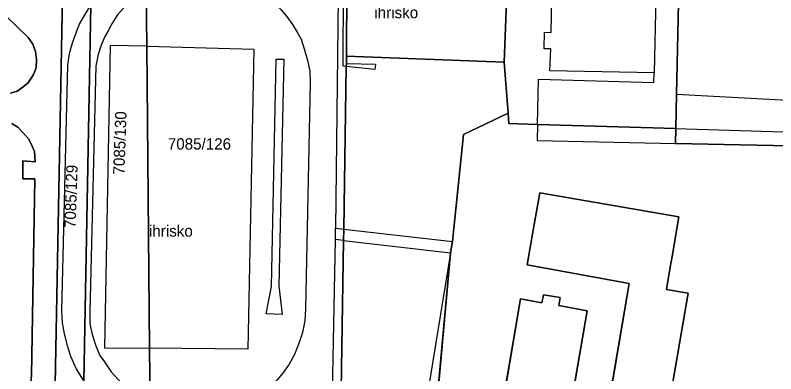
# Model space of a CAD drawing. Extents: x -266199 to -261993, y -1239047 to -1235108.
# Drawn here: x -263730.4 to -263596.4, y -1236847.2 to -1236783.9 of the extents above; entities that cross this region are included whole.
import ezdxf

# ---------------------------------------------------------------- set-up
doc = ezdxf.new("R2010")
doc.units = 0
for name, color, linetype in [('body_kn', 7, 'Continuous'), ('kladpar_druhypozemkov', 7, 'Continuous'), ('kladpar_hranice', 7, 'Continuous'), ('kladpar_parcelnecisla', 7, 'Continuous'), ('kladpar_plochy', 7, 'Continuous'), ('popisy', 7, 'Continuous'), ('zappar_hrandruhpozemk', 7, 'Continuous')]:
    doc.layers.add(name, color=color, linetype=linetype)

msp = doc.modelspace()

# ---------------------------------------------------------------- linework, layer by layer
at = {"layer": 'body_kn'}
for p, q in [((-263718.29, -1236783.97), (-263718.29, -1236783.97)), ((-263682.58, -1236784.11), (-263682.58, -1236784.11)), ((-263719.06, -1236785.4), (-263719.06, -1236785.4)), ((-263713.37, -1236785.44), (-263713.37, -1236785.44)), ((-263681.54, -1236785.56), (-263681.54, -1236785.56)), ((-263719.68, -1236786.89), (-263719.68, -1236786.89)), ((-263714.04, -1236786.68), (-263714.04, -1236786.68)), ((-263680.73, -1236786.92), (-263680.73, -1236786.92)), ((-263637.13, -1236786.94), (-263637.13, -1236786.94)), ((-263635.93, -1236786.95), (-263635.93, -1236786.95)), ((-263728.11, -1236787.85), (-263728.11, -1236787.85)), ((-263714.66, -1236787.82), (-263714.66, -1236787.82)), ((-263680.03, -1236788.17), (-263680.03, -1236788.17)), ((-263727.28, -1236789.04), (-263727.28, -1236789.04)), ((-263720.38, -1236788.88), (-263720.38, -1236788.88)), ((-263715.33, -1236789.41), (-263715.33, -1236789.41)), ((-263713.67, -1236789.25), (-263713.67, -1236789.25)), ((-263707.24, -1236789.41), (-263707.24, -1236789.41)), ((-263707.24, -1236789.41), (-263707.24, -1236789.41)), ((-263688.35, -1236789.89), (-263688.35, -1236789.89)), ((-263679.51, -1236789.88), (-263679.51, -1236789.88)), ((-263637.21, -1236789.85), (-263637.21, -1236789.85)), ((-263637.21, -1236789.85), (-263637.21, -1236789.85)), ((-263635.99, -1236789.88), (-263635.99, -1236789.88)), ((-263726.83, -1236790.3), (-263726.83, -1236790.3)), ((-263720.91, -1236790.74), (-263720.91, -1236790.74)), ((-263715.77, -1236790.87), (-263715.77, -1236790.87)), ((-263672.59, -1236791.13), (-263672.59, -1236791.13)), ((-263672.04, -1236791.15), (-263672.04, -1236791.15)), ((-263726.64, -1236791.75), (-263726.64, -1236791.75)), ((-263721.22, -1236792.66), (-263721.22, -1236792.66)), ((-263684.44, -1236791.69), (-263684.44, -1236791.69)), ((-263684.44, -1236791.69), (-263684.44, -1236791.69)), ((-263683.06, -1236791.7), (-263683.06, -1236791.7)), ((-263678.98, -1236791.69), (-263678.98, -1236791.69)), ((-263672.05, -1236792.41), (-263672.05, -1236792.41)), ((-263672.05, -1236792.41), (-263672.05, -1236792.41)), ((-263666.94, -1236792.53), (-263666.94, -1236792.53)), ((-263644.25, -1236792.2), (-263644.25, -1236792.2)), ((-263644.25, -1236792.2), (-263644.25, -1236792.2)), ((-263726.7, -1236793.22), (-263726.7, -1236793.22)), ((-263716.19, -1236792.87), (-263716.19, -1236792.87)), ((-263678.48, -1236793.75), (-263678.48, -1236793.75)), ((-263672.6, -1236792.93), (-263672.6, -1236792.93)), ((-263672.06, -1236792.98), (-263672.06, -1236792.98)), ((-263672.06, -1236792.98), (-263672.06, -1236792.98)), ((-263667.03, -1236793.48), (-263667.03, -1236793.48)), ((-263636.21, -1236793.75), (-263636.21, -1236793.75)), ((-263617.81, -1236794.08), (-263617.81, -1236794.08)), ((-263617.81, -1236794.08), (-263617.81, -1236794.08)), ((-263727.21, -1236794.39), (-263727.21, -1236794.39)), ((-263638.16, -1236795.18), (-263638.16, -1236795.18)), ((-263729.25, -1236796.75), (-263729.25, -1236796.75)), ((-263728.16, -1236795.86), (-263728.16, -1236795.86)), ((-263678.44, -1236795.8), (-263678.44, -1236795.8)), ((-263617.87, -1236795.8), (-263617.87, -1236795.8)), ((-263730.07, -1236797.34), (-263730.07, -1236797.34)), ((-263613.84, -1236797.84), (-263613.84, -1236797.84)), ((-263613.84, -1236797.84), (-263613.84, -1236797.84)), ((-263643.55, -1236801.17), (-263643.55, -1236801.17)), ((-263643.55, -1236801.17), (-263643.55, -1236801.17)), ((-263643.41, -1236803.03), (-263643.41, -1236803.03)), ((-263638.37, -1236803.18), (-263638.37, -1236803.18)), ((-263638.37, -1236803.18), (-263638.37, -1236803.18)), ((-263729.93, -1236803.67), (-263729.93, -1236803.67)), ((-263729.01, -1236804.68), (-263729.01, -1236804.68)), ((-263613.97, -1236803.91), (-263613.97, -1236803.91)), ((-263613.97, -1236803.91), (-263613.97, -1236803.91)), ((-263728, -1236805.76), (-263728, -1236805.76)), ((-263651.4, -1236804.98), (-263651.4, -1236804.98)), ((-263638.44, -1236806.04), (-263638.44, -1236806.04)), ((-263727.43, -1236806.99), (-263727.43, -1236806.99)), ((-263614.03, -1236806.55), (-263614.03, -1236806.55)), ((-263727.02, -1236807.93), (-263727.02, -1236807.93)), ((-263729.06, -1236809.61), (-263729.06, -1236809.61)), ((-263726.9, -1236809.79), (-263726.9, -1236809.79)), ((-263729.08, -1236812.8), (-263729.08, -1236812.8)), ((-263726.97, -1236812.77), (-263726.97, -1236812.77)), ((-263637.97, -1236815.26), (-263637.97, -1236815.26)), ((-263613.45, -1236819.48), (-263613.45, -1236819.48)), ((-263673.95, -1236821.5), (-263673.95, -1236821.5)), ((-263673.95, -1236821.5), (-263673.95, -1236821.5)), ((-263672.51, -1236821.66), (-263672.51, -1236821.66)), ((-263672.51, -1236821.66), (-263672.51, -1236821.66)), ((-263639.13, -1236821.86), (-263639.13, -1236821.86)), ((-263673.98, -1236823.48), (-263673.98, -1236823.48)), ((-263673.98, -1236823.48), (-263673.98, -1236823.48)), ((-263672.54, -1236823.65), (-263672.54, -1236823.65)), ((-263672.54, -1236823.65), (-263672.54, -1236823.65)), ((-263653.36, -1236823.82), (-263653.36, -1236823.82)), ((-263653.36, -1236823.82), (-263653.36, -1236823.82)), ((-263653.7, -1236825.82), (-263653.7, -1236825.82)), ((-263653.7, -1236825.82), (-263653.7, -1236825.82)), ((-263614.65, -1236826.47), (-263614.65, -1236826.47)), ((-263640.21, -1236827.97), (-263640.21, -1236827.97)), ((-263614.97, -1236828.35), (-263614.97, -1236828.35)), ((-263683.97, -1236831.63), (-263683.97, -1236831.63)), ((-263622.19, -1236831.21), (-263622.19, -1236831.21)), ((-263685.27, -1236831.75), (-263685.27, -1236831.75)), ((-263615.64, -1236832.29), (-263615.64, -1236832.29)), ((-263611.83, -1236832.93), (-263611.83, -1236832.93)), ((-263641.34, -1236833.95), (-263641.34, -1236833.95)), ((-263637.33, -1236833.24), (-263637.33, -1236833.24)), ((-263634.35, -1236833.71), (-263634.35, -1236833.71)), ((-263637.58, -1236834.64), (-263637.58, -1236834.64)), ((-263634.61, -1236835.1), (-263634.61, -1236835.1)), ((-263722.25, -1236836.07), (-263722.25, -1236836.07)), ((-263717.28, -1236836.22), (-263717.28, -1236836.22)), ((-263686.18, -1236836.61), (-263686.18, -1236836.61)), ((-263683.38, -1236836.73), (-263683.38, -1236836.73)), ((-263679.27, -1236835.7), (-263679.27, -1236835.7)), ((-263629.6, -1236836.05), (-263629.6, -1236836.05)), ((-263722.14, -1236838.2), (-263722.14, -1236838.2)), ((-263679.36, -1236837.83), (-263679.36, -1236837.83)), ((-263717.26, -1236838.35), (-263717.26, -1236838.35)), ((-263721.78, -1236840.13), (-263721.78, -1236840.13)), ((-263716.88, -1236840.25), (-263716.88, -1236840.25)), ((-263679.77, -1236839.91), (-263679.77, -1236839.91)), ((-263721.25, -1236842.16), (-263721.25, -1236842.16)), ((-263716.19, -1236842.21), (-263716.19, -1236842.21)), ((-263680.34, -1236841.67), (-263680.34, -1236841.67)), ((-263714.67, -1236842.58), (-263714.67, -1236842.58)), ((-263706.72, -1236842.67), (-263706.72, -1236842.67)), ((-263689.42, -1236842.85), (-263689.42, -1236842.85)), ((-263720.66, -1236844.07), (-263720.66, -1236844.07)), ((-263715.52, -1236843.93), (-263715.52, -1236843.93)), ((-263714.65, -1236845.04), (-263714.65, -1236845.04)), ((-263681.2, -1236843.77), (-263681.2, -1236843.77)), ((-263682.14, -1236845.45), (-263682.14, -1236845.45)), ((-263719.61, -1236846.4), (-263719.61, -1236846.4)), ((-263713.49, -1236846.79), (-263713.49, -1236846.79)), ((-263683.3, -1236847.09), (-263683.3, -1236847.09))]:
    msp.add_line(p, q, dxfattribs=at)
at = {"layer": 'kladpar_druhypozemkov'}
for p, q in [((-263711.77, -1236797.65), (-263711.77, -1236797.65)), ((-263697.3, -1236804.4), (-263697.3, -1236804.4)), ((-263719.74, -1236806.9), (-263719.74, -1236806.9)), ((-263665.1, -1236846.68), (-263665.1, -1236846.68))]:
    msp.add_line(p, q, dxfattribs=at)
at = {"layer": 'kladpar_hranice'}
for points in [[(-263613.84, -1236797.84), (-263612.64, -1236741.89), (-263612.51, -1236735.84), (-263583.74, -1236736.71), (-263585.19, -1236799.38), (-263585.32, -1236804.77), (-263585.37, -1236807.14), (-263614.03, -1236806.55), (-263613.97, -1236803.91), (-263613.84, -1236797.84)], [(-263612.64, -1236741.89), (-263613.84, -1236797.84), (-263613.97, -1236803.91), (-263638.37, -1236803.18), (-263643.41, -1236803.03), (-263643.55, -1236801.17), (-263644.25, -1236792.2), (-263643.85, -1236781.56)], [(-263716.7, -1236751.08), (-263717.28, -1236752.66), (-263717.14, -1236754.36), (-263721.61, -1236755.64), (-263721.75, -1236763.12), (-263721.85, -1236768.12), (-263723.45, -1236852.13), (-263724.24, -1236852.11)], [(-263707.61, -1236751.73), (-263707.61, -1236752.17), (-263707.61, -1236752.3), (-263707.57, -1236756.49), (-263707.39, -1236773.99), (-263707.34, -1236779.59), (-263707.24, -1236789.41), (-263706.72, -1236842.67), (-263706.62, -1236852.4), (-263706.58, -1236856.95)], [(-263706.58, -1236856.95), (-263706.62, -1236852.4), (-263706.72, -1236842.67), (-263707.24, -1236789.41), (-263707.34, -1236779.59), (-263707.39, -1236773.99), (-263707.57, -1236756.49), (-263707.61, -1236752.3), (-263707.61, -1236752.17), (-263707.61, -1236751.73)], [(-263705.51, -1236751.38), (-263705.53, -1236751.84), (-263705.62, -1236754.9), (-263706.11, -1236770.94), (-263678.03, -1236773.3), (-263673.4, -1236773.69), (-263672.79, -1236773.74), (-263672.84, -1236777.74), (-263671.99, -1236777.71), (-263671.99, -1236778.61), (-263672.04, -1236791.15), (-263672.05, -1236792.41), (-263672.06, -1236792.98), (-263672.51, -1236821.66), (-263672.54, -1236823.65), (-263673.08, -1236857.59), (-263673.25, -1236874.56), (-263674.92, -1236874.56), (-263680.06, -1236874.56), (-263682.17, -1236874.56), (-263704.55, -1236858.41), (-263706.58, -1236856.95)], [(-263717.14, -1236754.36), (-263716.6, -1236754.28), (-263716.7, -1236759.25), (-263716.78, -1236763.99), (-263717.11, -1236782.13), (-263718.32, -1236848.48), (-263718.46, -1236856.19), (-263723.45, -1236852.13), (-263721.85, -1236768.12), (-263721.75, -1236763.12), (-263721.61, -1236755.64), (-263717.14, -1236754.36)], [(-263706.58, -1236856.95), (-263718.32, -1236848.48), (-263717.11, -1236782.13), (-263716.78, -1236763.99), (-263716.7, -1236759.25), (-263716.6, -1236754.28)], [(-263643.85, -1236781.56), (-263644.25, -1236792.2), (-263672.04, -1236791.15), (-263671.99, -1236778.61)], [(-263731.24, -1236797.68), (-263730.07, -1236797.34), (-263729.25, -1236796.75), (-263728.16, -1236795.86), (-263727.21, -1236794.39), (-263726.7, -1236793.22), (-263726.64, -1236791.75), (-263726.83, -1236790.3), (-263727.28, -1236789.04), (-263728.11, -1236787.85), (-263732.1, -1236783.97)], [(-263732.1, -1236783.97), (-263728.11, -1236787.85), (-263727.28, -1236789.04), (-263726.83, -1236790.3), (-263726.64, -1236791.75), (-263726.7, -1236793.22), (-263727.21, -1236794.39), (-263728.16, -1236795.86), (-263729.25, -1236796.75), (-263730.07, -1236797.34), (-263731.24, -1236797.68)], [(-263706.58, -1236856.95), (-263704.55, -1236858.41), (-263682.17, -1236874.56), (-263680.06, -1236874.56), (-263674.92, -1236874.56), (-263673.25, -1236874.56), (-263673.08, -1236857.59), (-263672.54, -1236823.65), (-263672.51, -1236821.66), (-263672.06, -1236792.98), (-263672.05, -1236792.41), (-263672.04, -1236791.15), (-263644.25, -1236792.2)], [(-263644.25, -1236792.2), (-263643.55, -1236801.17), (-263651.4, -1236804.98), (-263653.36, -1236823.82), (-263653.7, -1236825.82), (-263657.83, -1236871.66), (-263659.27, -1236887.66), (-263659.67, -1236888.98)], [(-263659.67, -1236888.98), (-263659.27, -1236887.66), (-263657.83, -1236871.66), (-263653.7, -1236825.82), (-263653.36, -1236823.82), (-263651.4, -1236804.98), (-263643.55, -1236801.17)], [(-263643.55, -1236801.17), (-263643.41, -1236803.03), (-263638.37, -1236803.18), (-263613.97, -1236803.91), (-263614.03, -1236806.55), (-263585.37, -1236807.14), (-263579.23, -1236807.27), (-263579.09, -1236804.96), (-263566.69, -1236804.81), (-263568.91, -1236807.57), (-263570.28, -1236812.26), (-263570.64, -1236814.85), (-263598.28, -1236906.87), (-263599.02, -1236908.76)], [(-263730.99, -1236803.01), (-263729.93, -1236803.67), (-263729.01, -1236804.68), (-263728, -1236805.76), (-263727.43, -1236806.99), (-263727.02, -1236807.93), (-263726.9, -1236809.79), (-263729.06, -1236809.61), (-263729.08, -1236812.8), (-263726.97, -1236812.77), (-263727.57, -1236847.41), (-263727.8, -1236849.96), (-263728.66, -1236852.26)], [(-263724.24, -1236852.11), (-263728.66, -1236852.26), (-263727.8, -1236849.96), (-263727.57, -1236847.41), (-263726.97, -1236812.77), (-263729.08, -1236812.8), (-263729.06, -1236809.61), (-263726.9, -1236809.79), (-263727.02, -1236807.93), (-263727.43, -1236806.99), (-263728, -1236805.76), (-263729.01, -1236804.68), (-263729.93, -1236803.67), (-263730.99, -1236803.01)], [(-263616.14, -1236858.2), (-263611.83, -1236832.93), (-263615.64, -1236832.29), (-263614.97, -1236828.35), (-263614.65, -1236826.47), (-263613.45, -1236819.48), (-263637.97, -1236815.26), (-263639.13, -1236821.86), (-263640.21, -1236827.97), (-263622.19, -1236831.21), (-263626.23, -1236855)], [(-263626.23, -1236855), (-263622.19, -1236831.21), (-263640.21, -1236827.97), (-263639.13, -1236821.86), (-263637.97, -1236815.26), (-263613.45, -1236819.48), (-263614.65, -1236826.47), (-263614.97, -1236828.35), (-263615.64, -1236832.29), (-263611.83, -1236832.93), (-263616.14, -1236858.2)], [(-263632.67, -1236853.87), (-263629.6, -1236836.05), (-263634.61, -1236835.1), (-263634.35, -1236833.71), (-263637.33, -1236833.24), (-263637.58, -1236834.64), (-263641.34, -1236833.95), (-263646.51, -1236864.27)], [(-263646.51, -1236864.27), (-263641.34, -1236833.95), (-263637.58, -1236834.64), (-263637.33, -1236833.24), (-263634.35, -1236833.71), (-263634.61, -1236835.1), (-263629.6, -1236836.05), (-263632.67, -1236853.87)]]:
    msp.add_lwpolyline(points, dxfattribs=at)
at = {"layer": 'kladpar_plochy'}
for p, q in [((-263651.4, -1236804.98), (-263643.55, -1236801.17)), ((-263643.55, -1236801.17), (-263643.41, -1236803.03)), ((-263643.41, -1236803.03), (-263638.37, -1236803.18)), ((-263638.37, -1236803.18), (-263613.97, -1236803.91)), ((-263613.97, -1236803.91), (-263614.03, -1236806.55)), ((-263653.36, -1236823.82), (-263651.4, -1236804.98)), ((-263614.03, -1236806.55), (-263585.37, -1236807.14)), ((-263637.97, -1236815.26), (-263639.13, -1236821.86)), ((-263613.45, -1236819.48), (-263637.97, -1236815.26)), ((-263614.65, -1236826.47), (-263613.45, -1236819.48)), ((-263639.13, -1236821.86), (-263640.21, -1236827.97)), ((-263653.7, -1236825.82), (-263653.36, -1236823.82)), ((-263657.83, -1236871.66), (-263653.7, -1236825.82)), ((-263614.97, -1236828.35), (-263614.65, -1236826.47)), ((-263640.21, -1236827.97), (-263622.19, -1236831.21)), ((-263615.64, -1236832.29), (-263614.97, -1236828.35)), ((-263622.19, -1236831.21), (-263626.23, -1236855)), ((-263616.14, -1236858.2), (-263611.83, -1236832.93)), ((-263611.83, -1236832.93), (-263615.64, -1236832.29)), ((-263641.34, -1236833.95), (-263646.51, -1236864.27)), ((-263637.58, -1236834.64), (-263641.34, -1236833.95)), ((-263637.33, -1236833.24), (-263637.58, -1236834.64)), ((-263634.35, -1236833.71), (-263637.33, -1236833.24)), ((-263634.61, -1236835.1), (-263634.35, -1236833.71)), ((-263629.6, -1236836.05), (-263634.61, -1236835.1)), ((-263632.67, -1236853.87), (-263629.6, -1236836.05))]:
    msp.add_line(p, q, dxfattribs=at)
for points in [[(-263635.88, -1236722.21), (-263621.12, -1236719.13), (-263612.11, -1236717.26), (-263612.17, -1236719.74), (-263612.19, -1236721.02), (-263612.39, -1236730.32), (-263612.51, -1236735.84), (-263612.64, -1236741.89), (-263613.84, -1236797.84), (-263613.97, -1236803.91), (-263638.37, -1236803.18), (-263643.41, -1236803.03), (-263643.55, -1236801.17), (-263644.25, -1236792.2), (-263643.85, -1236781.56), (-263642.01, -1236781.55), (-263637.95, -1236781.74), (-263637.19, -1236749.91), (-263636.87, -1236743.09), (-263636.71, -1236739.62), (-263636.55, -1236736.35), (-263636.25, -1236729.99), (-263636.08, -1236726.31), (-263636.02, -1236724.85)], [(-263613.84, -1236797.84), (-263612.64, -1236741.89), (-263612.51, -1236735.84), (-263583.74, -1236736.71), (-263585.19, -1236799.38), (-263585.32, -1236804.77), (-263585.37, -1236807.14), (-263614.03, -1236806.55), (-263613.97, -1236803.91)], [(-263716.6, -1236754.28), (-263714.28, -1236753.91), (-263712.21, -1236752.83), (-263709.64, -1236752.07), (-263707.61, -1236751.73), (-263707.61, -1236752.17), (-263707.61, -1236752.3), (-263707.57, -1236756.49), (-263707.39, -1236773.99), (-263707.34, -1236779.59), (-263707.24, -1236789.41), (-263706.72, -1236842.67), (-263706.62, -1236852.4), (-263706.58, -1236856.95), (-263718.32, -1236848.48), (-263717.11, -1236782.13), (-263716.78, -1236763.99), (-263716.7, -1236759.25)], [(-263717.14, -1236754.36), (-263716.6, -1236754.28), (-263716.7, -1236759.25), (-263716.78, -1236763.99), (-263717.11, -1236782.13), (-263718.32, -1236848.48), (-263718.46, -1236856.19), (-263723.45, -1236852.13), (-263721.85, -1236768.12), (-263721.75, -1236763.12), (-263721.61, -1236755.64)]]:
    msp.add_lwpolyline(points, close=True, dxfattribs=at)
for points in [[(-263732.25, -1236754.6), (-263726.83, -1236753.44), (-263722, -1236752.36), (-263716.7, -1236751.08), (-263717.28, -1236752.66), (-263717.14, -1236754.36), (-263721.61, -1236755.64), (-263721.75, -1236763.12), (-263721.85, -1236768.12), (-263723.45, -1236852.13), (-263724.24, -1236852.11), (-263728.66, -1236852.26), (-263727.8, -1236849.96), (-263727.57, -1236847.41), (-263726.97, -1236812.77), (-263729.08, -1236812.8), (-263729.06, -1236809.61), (-263726.9, -1236809.79), (-263727.02, -1236807.93), (-263727.43, -1236806.99), (-263728, -1236805.76), (-263729.01, -1236804.68), (-263729.93, -1236803.67), (-263730.99, -1236803.01)], [(-263671.99, -1236778.61), (-263672.04, -1236791.15), (-263672.05, -1236792.41), (-263672.06, -1236792.98), (-263672.51, -1236821.66), (-263672.54, -1236823.65), (-263673.08, -1236857.59), (-263673.25, -1236874.56), (-263674.92, -1236874.56), (-263680.06, -1236874.56), (-263682.17, -1236874.56), (-263704.55, -1236858.41), (-263706.58, -1236856.95), (-263706.62, -1236852.4), (-263706.72, -1236842.67), (-263707.24, -1236789.41), (-263707.34, -1236779.59)], [(-263643.85, -1236781.56), (-263644.25, -1236792.2), (-263672.04, -1236791.15), (-263671.99, -1236778.61)], [(-263731.24, -1236797.68), (-263730.07, -1236797.34), (-263729.25, -1236796.75), (-263728.16, -1236795.86), (-263727.21, -1236794.39), (-263726.7, -1236793.22), (-263726.64, -1236791.75), (-263726.83, -1236790.3), (-263727.28, -1236789.04), (-263728.11, -1236787.85), (-263732.1, -1236783.97)], [(-263732.1, -1236783.97), (-263728.11, -1236787.85), (-263727.28, -1236789.04), (-263726.83, -1236790.3), (-263726.64, -1236791.75), (-263726.7, -1236793.22), (-263727.21, -1236794.39), (-263728.16, -1236795.86), (-263729.25, -1236796.75), (-263730.07, -1236797.34), (-263731.24, -1236797.68)], [(-263673.08, -1236857.59), (-263672.54, -1236823.65), (-263672.51, -1236821.66), (-263672.06, -1236792.98), (-263672.05, -1236792.41), (-263672.04, -1236791.15), (-263644.25, -1236792.2), (-263643.55, -1236801.17), (-263651.4, -1236804.98), (-263653.36, -1236823.82), (-263653.7, -1236825.82), (-263657.83, -1236871.66)], [(-263730.99, -1236803.01), (-263729.93, -1236803.67), (-263729.01, -1236804.68), (-263728, -1236805.76), (-263727.43, -1236806.99), (-263727.02, -1236807.93), (-263726.9, -1236809.79), (-263729.06, -1236809.61), (-263729.08, -1236812.8), (-263726.97, -1236812.77), (-263727.57, -1236847.41), (-263727.8, -1236849.96), (-263728.66, -1236852.26), (-263737.21, -1236847.24)], [(-263626.23, -1236855), (-263622.19, -1236831.21), (-263640.21, -1236827.97), (-263639.13, -1236821.86), (-263637.97, -1236815.26), (-263613.45, -1236819.48), (-263614.65, -1236826.47), (-263614.97, -1236828.35), (-263615.64, -1236832.29), (-263611.83, -1236832.93), (-263616.14, -1236858.2)], [(-263646.51, -1236864.27), (-263641.34, -1236833.95), (-263637.58, -1236834.64), (-263637.33, -1236833.24), (-263634.35, -1236833.71), (-263634.61, -1236835.1), (-263629.6, -1236836.05), (-263632.67, -1236853.87)]]:
    msp.add_lwpolyline(points, dxfattribs=at)
at = {"layer": 'zappar_hrandruhpozemk'}
for p, q in [((-263635.93, -1236786.95), (-263635.21, -1236749.97)), ((-263616.89, -1236750.34), (-263617.81, -1236794.08)), ((-263673.45, -1236778.74), (-263673.95, -1236821.5)), ((-263672.59, -1236791.13), (-263672.52, -1236778.62)), ((-263713.37, -1236785.44), (-263714.04, -1236786.68)), ((-263713.67, -1236789.25), (-263714.67, -1236842.58)), ((-263707.24, -1236789.41), (-263713.67, -1236789.25)), ((-263707.24, -1236789.41), (-263688.35, -1236789.89)), ((-263688.35, -1236789.89), (-263689.42, -1236842.85)), ((-263721.22, -1236792.66), (-263722.25, -1236836.07)), ((-263685.27, -1236831.75), (-263684.44, -1236791.69)), ((-263672.05, -1236792.41), (-263666.94, -1236792.53)), ((-263666.94, -1236792.53), (-263667.03, -1236793.48)), ((-263716.19, -1236792.87), (-263717.28, -1236836.22)), ((-263667.03, -1236793.48), (-263672.06, -1236792.98)), ((-263617.87, -1236795.8), (-263617.81, -1236794.08)), ((-263638.37, -1236803.18), (-263638.16, -1236795.18)), ((-263638.16, -1236795.18), (-263617.87, -1236795.8)), ((-263678.44, -1236795.8), (-263679.27, -1236835.7)), ((-263613.84, -1236797.84), (-263585.19, -1236799.38)), ((-263638.37, -1236803.18), (-263638.44, -1236806.04)), ((-263613.97, -1236803.91), (-263585.32, -1236804.77)), ((-263638.44, -1236806.04), (-263614.03, -1236806.55)), ((-263673.98, -1236823.48), (-263673.95, -1236821.5)), ((-263673.95, -1236821.5), (-263672.51, -1236821.66)), ((-263672.51, -1236821.66), (-263653.36, -1236823.82)), ((-263674.92, -1236874.56), (-263673.98, -1236823.48)), ((-263672.54, -1236823.65), (-263673.98, -1236823.48)), ((-263672.54, -1236823.65), (-263653.7, -1236825.82)), ((-263653.36, -1236823.82), (-263653.7, -1236825.82)), ((-263653.7, -1236825.82), (-263660.92, -1236870.02)), ((-263714.67, -1236842.58), (-263706.72, -1236842.67)), ((-263689.42, -1236842.85), (-263706.72, -1236842.67)), ((-263714.65, -1236845.04), (-263713.49, -1236846.79))]:
    msp.add_line(p, q, dxfattribs=at)
for points in [[(-263691.72, -1236777.68), (-263690.15, -1236778.29), (-263688.86, -1236778.93), (-263687.38, -1236779.8), (-263686.11, -1236780.67), (-263684.83, -1236781.65), (-263683.65, -1236782.83), (-263682.58, -1236784.11), (-263681.54, -1236785.56), (-263680.73, -1236786.92), (-263680.03, -1236788.17), (-263679.51, -1236789.88), (-263678.98, -1236791.69), (-263678.48, -1236793.75), (-263678.44, -1236795.8)], [(-263707.34, -1236779.59), (-263707.48, -1236779.67), (-263708.62, -1236780.48), (-263709.9, -1236781.51), (-263711.3, -1236782.68), (-263712.37, -1236783.87), (-263713.37, -1236785.44)], [(-263717.11, -1236782.13), (-263717.33, -1236782.43), (-263718.29, -1236783.97), (-263719.06, -1236785.4), (-263719.68, -1236786.89), (-263720.38, -1236788.88), (-263720.91, -1236790.74), (-263721.22, -1236792.66)], [(-263714.04, -1236786.68), (-263714.66, -1236787.82), (-263715.33, -1236789.41), (-263715.77, -1236790.87), (-263716.19, -1236792.87)], [(-263637.21, -1236789.85), (-263637.13, -1236786.94), (-263635.93, -1236786.95)], [(-263617.81, -1236794.08), (-263636.21, -1236793.75), (-263635.99, -1236789.88), (-263637.21, -1236789.85)], [(-263672.06, -1236792.98), (-263672.6, -1236792.93), (-263672.59, -1236791.13)], [(-263684.44, -1236791.69), (-263683.06, -1236791.7), (-263683.97, -1236831.63), (-263683.38, -1236836.73), (-263686.18, -1236836.61), (-263685.27, -1236831.75)], [(-263722.25, -1236836.07), (-263722.14, -1236838.2), (-263721.78, -1236840.13), (-263721.25, -1236842.16), (-263720.66, -1236844.07), (-263719.61, -1236846.4), (-263718.56, -1236848.11), (-263718.32, -1236848.48)], [(-263717.28, -1236836.22), (-263717.26, -1236838.35), (-263716.88, -1236840.25), (-263716.19, -1236842.21), (-263715.52, -1236843.93), (-263714.65, -1236845.04)], [(-263679.27, -1236835.7), (-263679.36, -1236837.83), (-263679.77, -1236839.91), (-263680.34, -1236841.67), (-263681.2, -1236843.77), (-263682.14, -1236845.45), (-263683.3, -1236847.09), (-263684.26, -1236848.24), (-263685.66, -1236849.68)], [(-263713.49, -1236846.79), (-263712.27, -1236848.19), (-263710.86, -1236849.58), (-263709.38, -1236850.74), (-263707.81, -1236851.82), (-263706.62, -1236852.4)]]:
    msp.add_lwpolyline(points, dxfattribs=at)

# ---------------------------------------------------------------- texts
at = {"layer": 'kladpar_parcelnecisla'}
for s, p in [('7085/130', (-263711.17, -1236812.05)), ('7085/129', (-263719.78, -1236821.49))]:
    msp.add_text(s, height=2, rotation=88, dxfattribs=at).set_placement(p)
msp.add_text('7085/126', height=2, dxfattribs=at).set_placement((-263703.52, -1236807.62))
at = {"layer": 'popisy'}
for p in [(-263667.12, -1236784.46), (-263706.84, -1236822.97)]:
    msp.add_text('ihrisko', height=2, dxfattribs=at).set_placement(p)

doc.saveas('drawing.dxf')
